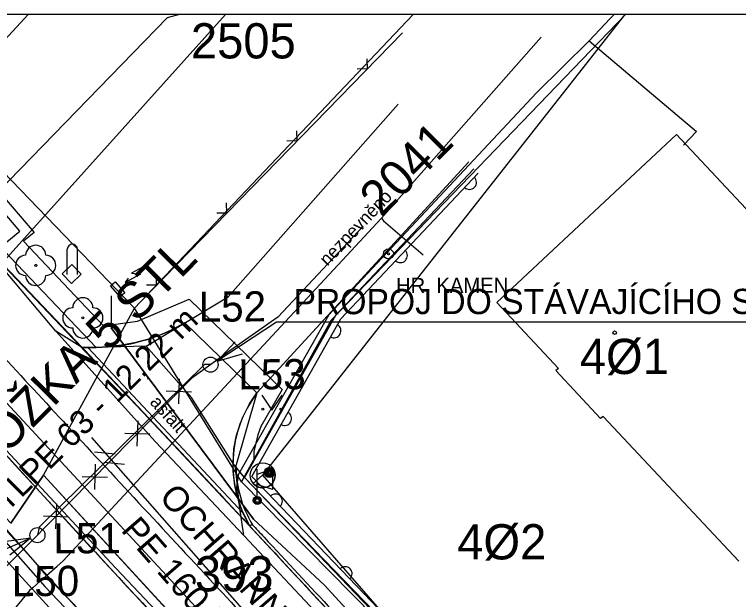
# Model space of a CAD drawing. Extents: x -643342 to -638635, y -1201752 to -1189948.
# Drawn here: x -639576.01 to -639540.06, y -1192545.93 to -1192516.87 of the extents above; entities that cross this region are included whole.
import ezdxf

# ---------------------------------------------------------------- set-up
doc = ezdxf.new("R2010")
doc.units = 0
for name, color, linetype in [('2', 7, 'Continuous'), ('41', 7, 'Continuous'), ('42', 7, 'Continuous'), ('IS_EL_NN_NADZEMNÍ', 7, 'Continuous'), ('IS_PLYN_STL', 7, 'Continuous'), ('IS_TELEF_BYVALY_DALKOVY_METALICKY', 7, 'Continuous'), ('IS_TELEF_MISTNI_ZAMERENO', 7, 'Continuous'), ('IS_VODOVOD_PRIPOJKA HYDRANT', 7, 'Continuous'), ('IS_VODOVOD_VAS', 7, 'Continuous'), ('K-HRANICE_KN', 7, 'Continuous'), ('K-ČÍSLA_PARCEL', 7, 'Continuous'), ('N-CHODNIK', 7, 'Continuous'), ('N-KAN_DEST_TRASA-NÁVRH', 7, 'Continuous'), ('N-OBVOD STAVBY 06', 7, 'Continuous'), ('N-OSA', 7, 'Continuous'), ('N-pasova vpust', 7, 'Continuous'), ('N-rusene_vedeni', 7, 'Continuous'), ('N-SILNICE', 7, 'Continuous'), ('N-SJEZDY', 7, 'Continuous'), ('N-SRAFY_PLOCHY', 7, 'Continuous'), ('RWE_STL_RADY', 7, 'Continuous'), ('tomaštík - Džuganovi - Vrstva 36', 7, 'Continuous'), ('Vrstva 13', 7, 'Continuous'), ('Vrstva 46', 7, 'Continuous'), ('Z-hrany_a_čáry', 7, 'Continuous'), ('Z-popisy', 7, 'Continuous'), ('Z-sloupy', 7, 'Continuous'), ('Z-stromy', 7, 'Continuous'), ('Z-VO_rozhlas', 7, 'Continuous'), ('Z-značky', 7, 'Continuous')]:
    doc.layers.add(name, color=color, linetype=linetype)

# ---------------------------------------------------------------- blocks, each defined once
blk = doc.blocks.new('RAMA24')
at = {"layer": 'Vrstva 13'}
blk.add_line((0, 14850), (-29700, 14850), dxfattribs=at)

msp = doc.modelspace()

# ---------------------------------------------------------------- linework, layer by layer
at = {"layer": '2'}
for centre in [(-639566.271, -1192534.261), (-639574.866, -1192542.736)]:
    msp.add_circle(centre, 0.375, dxfattribs=at)
at = {"layer": '42'}
for p, q in [((-639562.996, -1192532.151), (-639565.937, -1192534.091)), ((-639509.35, -1192532.151), (-639562.996, -1192532.151)), ((-639565.937, -1192534.091), (-639565.051, -1192533.129)), ((-639565.937, -1192534.091), (-639564.683, -1192533.721)), ((-639572.181, -1192537.888), (-639554.057, -1192558.462)), ((-639572.038, -1192538.589), (-639571.001, -1192538.687)), ((-639571.574, -1192539.115), (-639570.538, -1192539.214)), ((-639579.577, -1192544.783), (-639575.209, -1192542.888)), ((-639575.209, -1192542.888), (-639576.517, -1192543.066)), ((-639575.209, -1192542.888), (-639576.232, -1192543.722))]:
    msp.add_line(p, q, dxfattribs=at)
at = {"layer": 'IS_EL_NN_NADZEMNÍ'}
for p, q in [((-639563.68, -1192539.76), (-639545.681, -1192516.865)), ((-639564.153, -1192540.161), (-639563.22, -1192539.345)), ((-639548.65, -1192556.96), (-639563.68, -1192539.76))]:
    msp.add_line(p, q, dxfattribs=at)
msp.add_lwpolyline([(-639563.22, -1192539.345), (-639564.153, -1192540.161)], dxfattribs=at)
msp.add_circle((-639563.68, -1192539.76), 0.62, dxfattribs=at)
for centre, radius, start, end in [((-639563.68, -1192539.76), 0.62, 220.2153, 41.1343), ((-639563.674, -1192539.785), 0.633, 43.2142, 44.1384)]:
    msp.add_arc(centre, radius, start, end, dxfattribs=at)
at = {"layer": 'IS_PLYN_STL'}
msp.add_lwpolyline([(-639558.7, -1192527.379), (-639562.93, -1192531.91), (-639565.31, -1192533.57), (-639567.2, -1192534.93), (-639575.22, -1192543.1), (-639580.69, -1192548.54), (-639581, -1192548.87), (-639580.76, -1192549.12), (-639580.04, -1192550), (-639579.72, -1192550.39)], dxfattribs=at)
at = {"layer": 'IS_TELEF_BYVALY_DALKOVY_METALICKY'}
msp.add_lwpolyline([(-639637.691, -1192595.092), (-639636.465, -1192593.912), (-639627.394, -1192585.745), (-639565.52, -1192516.865)], dxfattribs=at)
at = {"layer": 'IS_TELEF_MISTNI_ZAMERENO'}
for p, q in [((-639568.42, -1192517.04), (-639576.93, -1192525.79)), ((-639567.81, -1192516.865), (-639568.42, -1192517.04)), ((-639546.42, -1192517.07), (-639547.47, -1192518.17)), ((-639547.47, -1192518.17), (-639546.42, -1192517.07)), ((-639546.227, -1192516.865), (-639546.42, -1192517.07)), ((-639547.47, -1192518.17), (-639550.08, -1192520.75)), ((-639550.08, -1192520.75), (-639547.47, -1192518.17)), ((-639547.47, -1192518.17), (-639542.14, -1192522.68)), ((-639550.08, -1192520.75), (-639560.4, -1192531.78)), ((-639542.14, -1192522.68), (-639542.78, -1192523.35)), ((-639571.2, -1192530.84), (-639571.2, -1192532.28)), ((-639560.4, -1192531.78), (-639564.9, -1192539.73)), ((-639571.2, -1192532.28), (-639571.2, -1192532.43)), ((-639571.2, -1192532.43), (-639565.03, -1192540.73)), ((-639565.03, -1192540.73), (-639571.2, -1192532.43)), ((-639564.9, -1192539.73), (-639565.03, -1192540.73)), ((-639565.03, -1192540.73), (-639564.13, -1192541.94)), ((-639564.13, -1192541.94), (-639565.03, -1192540.73)), ((-639564.13, -1192541.94), (-639560.62, -1192545.22)), ((-639560.62, -1192545.22), (-639552.49, -1192553.95)), ((-639552.49, -1192553.95), (-639560.62, -1192545.22))]:
    msp.add_line(p, q, dxfattribs=at)
at = {"layer": 'IS_VODOVOD_PRIPOJKA HYDRANT'}
msp.add_lwpolyline([(-639557.79, -1192526.98), (-639557.68, -1192527.11), (-639555.72, -1192528.81)], dxfattribs=at)
at = {"layer": 'IS_VODOVOD_VAS'}
for points in [[(-639585.016, -1192516.865), (-639582.734, -1192519.456), (-639590.76, -1192526.83), (-639574.966, -1192544.761)], [(-639584.373, -1192516.865), (-639581.86, -1192519.658), (-639589.96, -1192527.1), (-639576.881, -1192541.933), (-639574.75, -1192544.35), (-639574.64, -1192544.474)], [(-639549.85, -1192517.992), (-639557.79, -1192526.98), (-639573.609, -1192544.032)], [(-639573.884, -1192544.274), (-639573.609, -1192544.032)], [(-639574.409, -1192544.737), (-639574.64, -1192544.474)], [(-639574.409, -1192544.737), (-639573.884, -1192544.274)], [(-639574.966, -1192544.761), (-639574.735, -1192545.024)], [(-639574.56, -1192544.87), (-639574.735, -1192545.024)], [(-639574.56, -1192544.87), (-639574.409, -1192544.737)], [(-639574.409, -1192544.737), (-639574.178, -1192545)], [(-639575.085, -1192545.333), (-639574.735, -1192545.024)], [(-639574.735, -1192545.024), (-639574.504, -1192545.287)], [(-639574.178, -1192545), (-639565.32, -1192554.2), (-639544.196, -1192576.345), (-639543.991, -1192576.56), (-639543.73, -1192576.83), (-639534.504, -1192586.506), (-639531.24, -1192590.494), (-639527.133, -1192595.51), (-639522.796, -1192601.597), (-639522.77, -1192601.637), (-639518.91, -1192607.22), (-639515.881, -1192615.376)], [(-639575.085, -1192545.333), (-639575.259, -1192545.488), (-639576.018, -1192546.41)], [(-639574.504, -1192545.287), (-639565.62, -1192554.6), (-639534.876, -1192586.834), (-639527.527, -1192595.81), (-639523.229, -1192601.871), (-639519.29, -1192607.54), (-639519.07, -1192608.24), (-639516.818, -1192614.307), (-639515.63, -1192618.18), (-639513.05, -1192632.38), (-639511.6, -1192653.11)]]:
    msp.add_lwpolyline(points, dxfattribs=at)
at = {"layer": 'K-HRANICE_KN'}
for p, q in [((-639556.202, -1192516.865), (-639570.05, -1192531.45)), ((-639560.27, -1192532.04), (-639545.669, -1192516.865)), ((-639545.669, -1192516.865), (-639560.27, -1192532.04)), ((-639543.13, -1192522.82), (-639552.05, -1192531.18)), ((-639538.51, -1192527.78), (-639543.13, -1192522.82)), ((-639552.05, -1192531.18), (-639548.99, -1192534.45)), ((-639574.559, -1192539.749), (-639570.05, -1192531.45)), ((-639564.74, -1192540.08), (-639570.05, -1192531.45)), ((-639564.74, -1192540.08), (-639560.27, -1192532.04)), ((-639560.27, -1192532.04), (-639564.74, -1192540.08)), ((-639548.99, -1192534.45), (-639549.12, -1192534.56)), ((-639549.12, -1192534.56), (-639546.9, -1192536.94)), ((-639546.77, -1192536.83), (-639546.9, -1192536.94)), ((-639546.77, -1192536.83), (-639540.04, -1192544.03)), ((-639574.559, -1192539.749), (-639576.18, -1192542.14)), ((-639564.643, -1192550.549), (-639574.559, -1192539.749)), ((-639574.559, -1192539.749), (-639564.324, -1192550.911)), ((-639564.643, -1192550.549), (-639574.559, -1192539.749)), ((-639547.9, -1192557.16), (-639564.74, -1192540.08))]:
    msp.add_line(p, q, dxfattribs=at)
for points in [[(-639599.556, -1192516.865), (-639595.57, -1192521.25), (-639591.33, -1192525.9), (-639576.18, -1192542.14), (-639574.559, -1192539.749), (-639570.05, -1192531.45)], [(-639570.05, -1192531.45), (-639579.63, -1192521.52), (-639584.115, -1192516.865)], [(-639579.63, -1192521.52), (-639575.322, -1192516.865)]]:
    msp.add_lwpolyline(points, dxfattribs=at)
at = {"layer": 'K-ČÍSLA_PARCEL'}
msp.add_circle((-639546.205, -1192532.675), 0.0875, dxfattribs=at)
at = {"layer": 'N-CHODNIK'}
for p, q in [((-639564.59, -1192539.87), (-639565.161, -1192539.154)), ((-639547.94, -1192557.24), (-639564.59, -1192539.87))]:
    msp.add_line(p, q, dxfattribs=at)
at = {"layer": 'N-KAN_DEST_TRASA-NÁVRH'}
msp.add_lwpolyline([(-639583.962, -1192528.01), (-639550.452, -1192564.184), (-639529.583, -1192588.026), (-639514.491, -1192612.048), (-639507.737, -1192644.326), (-639498.832, -1192694.254), (-639511.439, -1192713.331), (-639516.613, -1192716.507), (-639553.938, -1192703.739), (-639570.485, -1192701.616), (-639578.687, -1192703.18)], dxfattribs=at)
at = {"layer": 'N-OBVOD STAVBY 06'}
for points in [[(-639580.824, -1192520.961), (-639575.028, -1192527.69), (-639575.555, -1192528.126), (-639571.584, -1192532.34), (-639569.898, -1192532.101), (-639567.334, -1192531.011), (-639562.714, -1192535.496), (-639563.777, -1192537.334), (-639563.916, -1192537.749), (-639564.117, -1192538.572), (-639564.127, -1192539.047), (-639564.59, -1192539.87), (-639556.157, -1192548.58), (-639547.851, -1192557.152), (-639546.37, -1192558.85), (-639546.295, -1192558.925), (-639542.755, -1192562.507)], [(-639532.853, -1192592.991), (-639532.948, -1192593.015), (-639536.515, -1192588.213), (-639537.119, -1192588.308), (-639546.267, -1192578.054), (-639553.229, -1192570.356), (-639556.749, -1192566.564), (-639568.569, -1192553.875), (-639568.389, -1192552.802), (-639591.813, -1192527.078)]]:
    msp.add_lwpolyline(points, dxfattribs=at)
at = {"layer": 'N-OSA'}
for centre, radius, start, end in [((-632515.845, -1186006.855), 9615.381, 222.7172805, 222.7768682), ((-635904.087, -1189140.863), 4999.951, 222.785271, 222.911144), ((-632042.643, -1185548.663), 10273.911, 222.9214561, 222.9772243)]:
    msp.add_arc(centre, radius, start, end, dxfattribs=at)
at = {"layer": 'N-pasova vpust'}
for p, q in [((-639572.638, -1192533.409), (-639564.321, -1192542.291)), ((-639572.363, -1192533.41), (-639572.62, -1192533.42)), ((-639572.509, -1192533.546), (-639564.926, -1192541.646)), ((-639572.363, -1192533.41), (-639564.639, -1192541.661)), ((-639564.639, -1192541.661), (-639564.321, -1192542.291))]:
    msp.add_line(p, q, dxfattribs=at)
at = {"layer": 'N-rusene_vedeni'}
for p, q in [((-639567.824, -1192534.963), (-639567.867, -1192536.212)), ((-639568.47, -1192535.566), (-639567.221, -1192535.609)), ((-639569.884, -1192537.061), (-639569.927, -1192538.31)), ((-639570.53, -1192537.664), (-639569.281, -1192537.707)), ((-639571.993, -1192539.21), (-639572.036, -1192540.46)), ((-639572.639, -1192539.813), (-639571.39, -1192539.857)), ((-639573.918, -1192541.171), (-639573.961, -1192542.42)), ((-639574.564, -1192541.774), (-639573.315, -1192541.817))]:
    msp.add_line(p, q, dxfattribs=at)
at = {"layer": 'N-SILNICE'}
for p, q in [((-639571.957, -1192533.403), (-639586.058, -1192518.599)), ((-639567.459, -1192538.912), (-639586.428, -1192518.935)), ((-639572.224, -1192543.332), (-639590.868, -1192523.025)), ((-639571.957, -1192533.403), (-639572.638, -1192533.409))]:
    msp.add_line(p, q, dxfattribs=at)
for centre, radius, start, end in [((-635904.087, -1189140.863), 4996.701, 222.848207, 222.911144), ((-635904.087, -1189140.863), 4996.551, 222.901263, 222.911144), ((-632043.168, -1185549.151), 10269.944, 222.9214551, 222.977221), ((-632042.268, -1185548.314), 10271.173, 222.9214572, 222.9772255), ((-632043.168, -1185549.151), 10269.794, 222.9214551, 222.977221), ((-635904.087, -1189140.863), 5003.201, 222.848207, 222.911144)]:
    msp.add_arc(centre, radius, start, end, dxfattribs=at)
at = {"layer": 'N-SJEZDY'}
for p, q in [((-639590.66, -1192526.86), (-639567.322, -1192552.488)), ((-639567.554, -1192532.191), (-639563.97, -1192535.67)), ((-639564.201, -1192542.2), (-639564.321, -1192542.291))]:
    msp.add_line(p, q, dxfattribs=at)
for centre, radius, start, end in [((-639572.022, -1192524.564), 8.84, 270.4205, 300.3567), ((-639559.21, -1192539.242), 5.952, 143.1133, 210.8121), ((-639559.21, -1192539.242), 5.802, 180.9853, 210.8121)]:
    msp.add_arc(centre, radius, start, end, dxfattribs=at)
at = {"layer": 'N-SRAFY_PLOCHY'}
for p, q in [((-639571.957, -1192533.403), (-639586.058, -1192518.599)), ((-639586.428, -1192518.935), (-639572.638, -1192533.409)), ((-639572.224, -1192543.332), (-639590.868, -1192523.025)), ((-639590.66, -1192526.86), (-639567.322, -1192552.488)), ((-639575.513, -1192530.429), (-639577.085, -1192528.775)), ((-639573.339, -1192532.719), (-639575.513, -1192530.429)), ((-639567.554, -1192532.191), (-639568.222, -1192532.545)), ((-639563.97, -1192535.67), (-639567.554, -1192532.191)), ((-639568.222, -1192532.545), (-639568.703, -1192532.757)), ((-639570.673, -1192535.496), (-639573.339, -1192532.719)), ((-639569.352, -1192532.991), (-639570.05, -1192533.181)), ((-639568.703, -1192532.757), (-639569.352, -1192532.991)), ((-639571.376, -1192533.38), (-639571.957, -1192533.403)), ((-639570.686, -1192533.302), (-639571.376, -1192533.38)), ((-639570.05, -1192533.181), (-639570.686, -1192533.302)), ((-639571.957, -1192533.403), (-639572.638, -1192533.409)), ((-639572.638, -1192533.409), (-639571.957, -1192533.403)), ((-639572.638, -1192533.409), (-639564.321, -1192542.291)), ((-639567.459, -1192538.912), (-639570.673, -1192535.496)), ((-639564.328, -1192536.205), (-639563.97, -1192535.67)), ((-639564.68, -1192536.899), (-639564.328, -1192536.205)), ((-639564.975, -1192537.767), (-639564.68, -1192536.899)), ((-639577.87, -1192537.183), (-639575.967, -1192539.256)), ((-639565.108, -1192538.45), (-639564.975, -1192537.767)), ((-639565.155, -1192539.159), (-639565.108, -1192538.45)), ((-639564.751, -1192541.829), (-639567.459, -1192538.912)), ((-639575.967, -1192539.256), (-639573.702, -1192541.704)), ((-639564.59, -1192539.87), (-639565.156, -1192539.16)), ((-639565.156, -1192539.16), (-639565.141, -1192539.731)), ((-639565.149, -1192539.562), (-639565.155, -1192539.159)), ((-639565.071, -1192540.275), (-639565.149, -1192539.562)), ((-639565.141, -1192539.731), (-639565.071, -1192540.275)), ((-639547.94, -1192557.24), (-639564.59, -1192539.87)), ((-639565.071, -1192540.275), (-639564.92, -1192540.921)), ((-639564.845, -1192541.132), (-639565.071, -1192540.275)), ((-639564.92, -1192540.921), (-639564.714, -1192541.506)), ((-639564.613, -1192541.726), (-639564.845, -1192541.132)), ((-639564.714, -1192541.506), (-639564.512, -1192541.946)), ((-639573.702, -1192541.704), (-639571.626, -1192543.976)), ((-639562.97, -1192543.744), (-639564.751, -1192541.829)), ((-639564.321, -1192542.291), (-639564.613, -1192541.726)), ((-639564.512, -1192541.946), (-639564.321, -1192542.291)), ((-639564.321, -1192542.291), (-639549.267, -1192558.458)), ((-639560.26, -1192546.656), (-639562.97, -1192543.744)), ((-639571.626, -1192543.976), (-639568.484, -1192547.359))]:
    msp.add_line(p, q, dxfattribs=at)
msp.add_arc((-635904.087, -1189140.863), 5003.201, 222.848207, 222.911144, dxfattribs=at)
at = {"layer": 'RWE_STL_RADY'}
msp.add_lwpolyline([(-639566.271, -1192534.261), (-639566.565, -1192534.259), (-639574.774, -1192542.328), (-639574.866, -1192542.736)], dxfattribs=at)
at = {"layer": 'Z-hrany_a_čáry'}
for p, q in [((-639556.74, -1192517.78), (-639569.82, -1192531.2)), ((-639558.485, -1192519.57), (-639558.491, -1192519.07)), ((-639558.485, -1192519.57), (-639558.986, -1192519.577)), ((-639575.74, -1192527.63), (-639581.2, -1192521.29)), ((-639565.4, -1192530.9), (-639556.96, -1192521.32)), ((-639561.975, -1192523.151), (-639561.981, -1192522.65)), ((-639561.975, -1192523.151), (-639562.475, -1192523.157)), ((-639553.45, -1192524.19), (-639563.97, -1192535.67)), ((-639560.05, -1192531.8), (-639553.2, -1192524.54)), ((-639559.807, -1192531.979), (-639552.982, -1192524.746)), ((-639565.465, -1192526.732), (-639565.471, -1192526.231)), ((-639565.465, -1192526.732), (-639565.965, -1192526.738)), ((-639576.67, -1192528.4), (-639575.74, -1192527.63)), ((-639573.95, -1192532.6), (-639577.2, -1192528.74)), ((-639573.64, -1192529.75), (-639573.154, -1192529.284)), ((-639573.154, -1192529.284), (-639572.694, -1192529.764)), ((-639573.18, -1192530.23), (-639573.64, -1192529.75)), ((-639572.694, -1192529.764), (-639573.18, -1192530.23)), ((-639571.24, -1192530.34), (-639571.014, -1192530.142)), ((-639571.014, -1192530.142), (-639570.524, -1192530.702)), ((-639568.955, -1192530.312), (-639568.961, -1192529.812)), ((-639570.75, -1192530.9), (-639571.24, -1192530.34)), ((-639568.955, -1192530.312), (-639569.455, -1192530.319)), ((-639570.524, -1192530.702), (-639570.75, -1192530.9)), ((-639569.47, -1192533.34), (-639565.4, -1192530.9)), ((-639564.59, -1192539.87), (-639560.05, -1192531.8)), ((-639564.219, -1192539.823), (-639559.807, -1192531.979)), ((-639569, -1192538.09), (-639573.95, -1192532.6)), ((-639572.62, -1192533.42), (-639573.95, -1192532.6)), ((-639569.47, -1192533.34), (-639572.62, -1192533.42)), ((-639567.22, -1192535.9), (-639569.47, -1192533.34)), ((-639570.98, -1192544.37), (-639580.87, -1192533.73)), ((-639565.03, -1192539.36), (-639567.22, -1192535.9)), ((-639563.97, -1192535.67), (-639565.03, -1192539.36)), ((-639564.61, -1192542.75), (-639569, -1192538.09)), ((-639564.83, -1192541.28), (-639565.03, -1192539.36)), ((-639547.94, -1192557.24), (-639564.59, -1192539.87)), ((-639547.723, -1192557.032), (-639564.219, -1192539.823)), ((-639564.61, -1192542.75), (-639564.83, -1192541.28)), ((-639543.49, -1192565.25), (-639564.61, -1192542.75)), ((-639563.45, -1192552.32), (-639570.98, -1192544.37))]:
    msp.add_line(p, q, dxfattribs=at)
for centre, start, end in [((-639553.416, -1192525.206), 226.6624, 46.6624), ((-639556.848, -1192528.843), 226.6624, 46.6624), ((-639560.144, -1192532.579), 240.6436, 60.6436), ((-639562.596, -1192536.937), 240.6436, 60.6436), ((-639563.051, -1192541.042), 313.7881, 133.7881), ((-639559.591, -1192544.651), 313.7881, 133.7881)]:
    msp.add_arc(centre, 0.35, start, end, dxfattribs=at)
at = {"layer": 'Z-sloupy'}
for centre, radius in [((-639557.44, -1192528.76), 0.25), ((-639557.44, -1192528.76), 0.05), ((-639563.35, -1192539.62), 0.25), ((-639563.35, -1192539.62), 0.2), ((-639563.35, -1192539.62), 0.15), ((-639563.35, -1192539.62), 0.1), ((-639563.35, -1192539.62), 0.05)]:
    msp.add_circle(centre, radius, dxfattribs=at)
at = {"layer": 'Z-stromy'}
for centre in [(-639574.95, -1192529.33), (-639572.61, -1192531.94)]:
    msp.add_circle(centre, 0.05, dxfattribs=at)
for centre, start, end in [((-639574.95, -1192528.83), 0, 180), ((-639575.45, -1192529.33), 90, 270), ((-639574.45, -1192529.33), 270, 90), ((-639574.95, -1192529.83), 180, 0), ((-639572.61, -1192531.44), 0, 180), ((-639573.11, -1192531.94), 90, 270), ((-639572.11, -1192531.94), 270, 90), ((-639572.61, -1192532.44), 180, 0)]:
    msp.add_arc(centre, 0.5, start, end, dxfattribs=at)
at = {"layer": 'Z-VO_rozhlas'}
for p, q in [((-639563.95, -1192540.81), (-639563.95, -1192539.46)), ((-639563.95, -1192539.71), (-639563.2, -1192539.46)), ((-639563.2, -1192539.46), (-639563.2, -1192540.46)), ((-639563.2, -1192540.46), (-639563.95, -1192540.21))]:
    msp.add_line(p, q, dxfattribs=at)
for radius in [0.2, 0.145, 0.0876]:
    msp.add_circle((-639563.95, -1192541.01), radius, dxfattribs=at)
at = {"layer": 'Z-značky'}
for p, q in [((-639573.381, -1192529.779), (-639573.381, -1192528.529)), ((-639572.881, -1192529.779), (-639572.881, -1192528.529)), ((-639569.648, -1192529.423), (-639570.197, -1192529.724)), ((-639569.747, -1192529.763), (-639570.516, -1192530.183)), ((-639570.197, -1192529.724), (-639569.747, -1192529.763)), ((-639570.353, -1192529.968), (-639570.516, -1192530.183)), ((-639570.516, -1192530.183), (-639570.248, -1192530.162)), ((-639563.719, -1192535.776), (-639563.219, -1192536.526)), ((-639563.219, -1192536.526), (-639562.719, -1192535.776))]:
    msp.add_line(p, q, dxfattribs=at)
for centre in [(-639563.669, -1192536.476), (-639562.77, -1192536.476)]:
    msp.add_circle(centre, 0.05, dxfattribs=at)
msp.add_arc((-639573.131, -1192528.529), 0.25, 0, 180, dxfattribs=at)

# ---------------------------------------------------------------- block references
at = {"layer": '41', "xscale": 0.01, "yscale": 0.01}
msp.add_blockref('RAMA24', (-639343.591, -1192665.365), dxfattribs=at)

# ---------------------------------------------------------------- texts
at = {"layer": '2'}
msp.add_text('PŘELOŽKA 5 STL', height=1.8, rotation=45.2919, dxfattribs=at).set_placement((-639580.852, -1192543.246))
at = {"layer": 'K-ČÍSLA_PARCEL'}
for s, p in [('2505', (-639567.245, -1192519.049)), ('4%%c1', (-639547.934, -1192534.729)), ('4%%c2', (-639554.021, -1192543.939)), ('393', (-639567.047, -1192545.526))]:
    msp.add_text(s, height=1.75, dxfattribs=at).set_placement(p)
msp.add_text('2041', height=1.75, rotation=45, dxfattribs=at).set_placement((-639557.79, -1192526.98))
at = {"layer": 'RWE_STL_RADY'}
msp.add_text('STLPE 63 - 12,22 m', height=1.2, rotation=44.7251, dxfattribs=at).set_placement((-639577.13, -1192542.369))
at = {"layer": 'tomaštík - Džuganovi - Vrstva 36'}
for s, rotation, p in [('PROPOJ DO STÁVAJÍCÍHO STL PLYNOVODU PE d 63', 0.0307, (-639562.148, -1192531.757)), ('OCHRANNÁ TRUBKA ', 311.0908, (-639568.872, -1192540.866)), ('PE 160 DÉLKA 7,7 m', 311.0908, (-639570.756, -1192542.509))]:
    msp.add_text(s, height=1.25, rotation=rotation, dxfattribs=at).set_placement(p)
at = {"layer": 'Vrstva 46'}
for s, p in [('L52', (-639566.856, -1192532.132)), ('L53', (-639564.89, -1192535.498)), ('L51', (-639574.069, -1192543.644)), ('L50', (-639576.136, -1192545.769))]:
    msp.add_text(s, height=1.5, rotation=0.301, dxfattribs=at).set_placement(p)
at = {"layer": 'Z-popisy'}
for s, height, rotation, p in [('nezpevněno', 0.65, 46.5336, (-639560.467, -1192529.397)), ('HR. KAMEN', 0.75, 0.0723, (-639557.061, -1192530.7)), ('asfalt', 0.65, 312.3484, (-639569.32, -1192536.158))]:
    msp.add_text(s, height=height, rotation=rotation, dxfattribs=at).set_placement(p)

doc.saveas('drawing.dxf')
